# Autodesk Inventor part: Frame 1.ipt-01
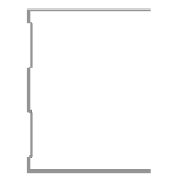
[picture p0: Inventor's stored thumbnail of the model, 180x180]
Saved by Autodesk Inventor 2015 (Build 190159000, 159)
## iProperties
Created: 2015-04
Part Number: Frame 1.ipt-01
Material: Aluminum 6061
Document SubType Name: Modeling
Standard: Unnamed
Designer: suporte
Language: en-US
Size Designation: (Unnamed 1)
Categories: <MemberInstance><Categories><Category DisplayName="Structural Shapes" InternalName="089c4875-fa83-4c05-b084-43b9cc11f5ed" Mnemonic="GRDR"><CategoryParameter Dis
Density: 2.7 g/cm^3
Appearance: Aluminum - Flat
IsCustomPart: 1
_CCFamilyMember: 1
_CCFamilyDisplayName: Frame 1
_FrameMemberDoc: Frame Member File
_Version: 15.0.0
_GetPNFromCC: 1
Author: suporte
G_L: 2100,000 mm
G_W: 70,000 mm
G_H: 75,000 mm
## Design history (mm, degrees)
node "Start Plane"
node "End Plane"
sketch "Sketch"
  geometry: L1 (34.6, 37.5)-(34.6, 36.7); L2 (34.6, 36.7)-(-34.6, 36.7); L3 (-34.6, -36.7)-(34.6, -36.7); L4 (34.6, -36.7)-(34.6, -37.5); L5 (34.6, -37.5)-(-35.4, -37.5); L6 (-35.4, 37.5)-(34.6, 37.5); L7 (-34.6, 36.7)-(-34.6, 31.7); L8 (-34.6, 31.7)-(-33.4, 30.5); L9 (-33.4, 30.5)-(-33.4, 10.746); L10 (-33.4, 10.746)-(-34.6, 9.546); L11 (-34.6, 9.546)-(-34.6, -9.546); L12 (-34.6, -9.546)-(-33.4, -10.746); L13 (-33.4, -10.746)-(-33.4, -30.5); L14 (-33.4, -30.5)-(-34.6, -31.7); L15 (-34.6, -31.7)-(-34.6, -36.7); L16 (-35.4, -37.5)-(-35.4, -31.369); L17 (-35.4, -31.369)-(-34.2, -30.169); L18 (-34.2, -30.169)-(-34.2, -11.077); L19 (-34.2, -11.077)-(-35.4, -9.877); L20 (-35.4, -9.877)-(-35.4, 9.877); L21 (-35.4, 9.877)-(-34.2, 11.077); L22 (-34.2, 11.077)-(-34.2, 30.169); L23 (-34.2, 30.169)-(-35.4, 31.369); L24 (-35.4, 31.369)-(-35.4, 37.5); L25 (-35.4, 0)-(30.37, 0); 3 further points
  constraints: 50 end point, 10 point on line, 9 parallel, 5 perpendicular, 4 equal length, 3 midpoint, 3 vertical, 2 vertical alignment, 1 collinear, 1 horizontal, 1 horizontal alignment
  dimensions: "d3" = 0.8 distance of L1.start L1.end; "d5" = 75 distance between parallel lines of L5 L6; "d6" = 0.8 distance between parallel lines of L24 L7; "d7" = 0.8 distance between parallel lines of L8 L23; "d8" = 0.8 distance between parallel lines of L22 L9; "d9" = 0.8 distance between parallel lines of L17 L14; "d10" = 0.8 distance between parallel lines of L13 L18; "d11" = 0.8 distance between parallel lines of L12 L19; "d12" = 0.8 distance between parallel lines of L21 L10; "d13" = 5 distance of L2.end L7.end; "d15" = 135 deg angle of L9 L8; "d16" = 2 distance between parallel lines of L24 L9; "d17" = 70 distance of L6.start L1.start
extrude "Body" join sketch "Sketch" stored distance "d24" = 0.13; taper "d25" = 0 deg
node "Driven Length"
  sketch "Sketch8"
    geometry: L1 (0, 0)-(10, 0) reference
    constraints: 2 end point, 1 horizontal
  workplane "Work Plane6"
  sketch "Sketch9"
    geometry: L1 (-2, 0)-(12, 0) reference; L2 (-2, 2100)-(12, 2100) reference
    dimensions: "d27" = 2100 distance between parallel lines of L1 L2 (derived)
body "Solid1"
other parameters: "G_OFFSET_START" = 0 [user parameter; used in 1 equation term], "G_OFFSET_END" = 0 [user parameter; used in 1 equation term], "d22" = 0 (computed from G_OFFSET_START), "G_L" = 2100 (= d27) [user parameter], "d32" = 90 deg
